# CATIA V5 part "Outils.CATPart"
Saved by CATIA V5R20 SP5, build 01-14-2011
Part number: Outils
Bounding box of the stored display mesh (mm): x -30 to 40, y -25 to 25, z -8 to 8
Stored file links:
  E:\IAO_2010\iao\IAO_MMS_Groupe2\IAO_MMS_Groupe2\flafosse\Catia\IAO\Outils.CATPart
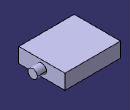
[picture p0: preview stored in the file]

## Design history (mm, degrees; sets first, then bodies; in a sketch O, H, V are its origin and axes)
Body1 (main body)
  Plane1 "Plan sup bâti": stored without definition
  Sketch1 on yz-plane, origin (0, 0, 0), H (0, 1, 0), V (0, 0, 1)
    line L1 (-25, 8) -> (25, 8)
    line L2 (25, 8) -> (25, -8)
    line L3 (25, -8) -> (-25, -8)
    line L4 (-25, -8) -> (-25, 8)
    reference intersected line E1 through (0, -8) direction (-1, 0) from Plane1
    reference intersected line E2 through (0, 0) direction (0, 1) from zx-plane
    reference intersected line E3 through (0, 0) direction (-1, 0) from xy-plane
    reference intersected line E4 through (0, 0) direction (0, 1) from zx-plane
    distance L2 E4 = 25
    horizontal: L1 H, L3 H
    vertical: L2 V, L4 V
    coincidence: L3 E1
    symmetry: L2 L4 E2, L1 L3 E3
  Pad1: profile Sketch1, direction (1, 0, 0), length 30, mirrored extent
  Plane2 "Plan sup bâti": stored without definition
  Sketch2 on end face of Pad1, origin (30, 0, 0), H (0, 1, 0), V (0, 0, 1)
    circle A1 centre (0, 0) radius 5
    radius A1 = 5
  Pad2: profile Sketch2, direction (1, 0, 0), length 10
  DatumCurve1
  DatumCurve2
  Sketch3 on Plane2, origin (0, 0, -8), H (1, 0, 0), V (0, 1, 0)
    line L1 (0, -254) -> (0, 246)
    point P1 (0, -254)
    point P2 (0, 246)
    reference projected line E1 (-30, 246) -> (30, 246) from edge of DatumCurve1
    reference projected line E2 (-30, -254) -> (30, -254) from edge of DatumCurve2
    coincidence: P1 V, P2 E1, P1 E2
    vertical: L1 V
